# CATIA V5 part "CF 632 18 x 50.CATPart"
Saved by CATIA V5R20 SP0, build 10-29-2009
Part number: CF 632 18 x 50
Definition: NONE
Nomenclature: CF 632 18 x 50
Source: Unknown
Description: CF 632 18 x 50
Bounding box of the stored display mesh (mm): x -13 to 37, y -17 to 17, z -17 to 17
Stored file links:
  C:\Users\Utente\Desktop\IO LAVORO\3D X SITO CF\X SITO\CF 632\CF 632 18 x 50.CATPart
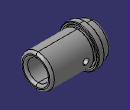
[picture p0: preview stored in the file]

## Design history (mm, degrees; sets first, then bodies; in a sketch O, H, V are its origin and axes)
Body1 "CF 632 18 x 50" (main body)
  Solid1: solid without history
